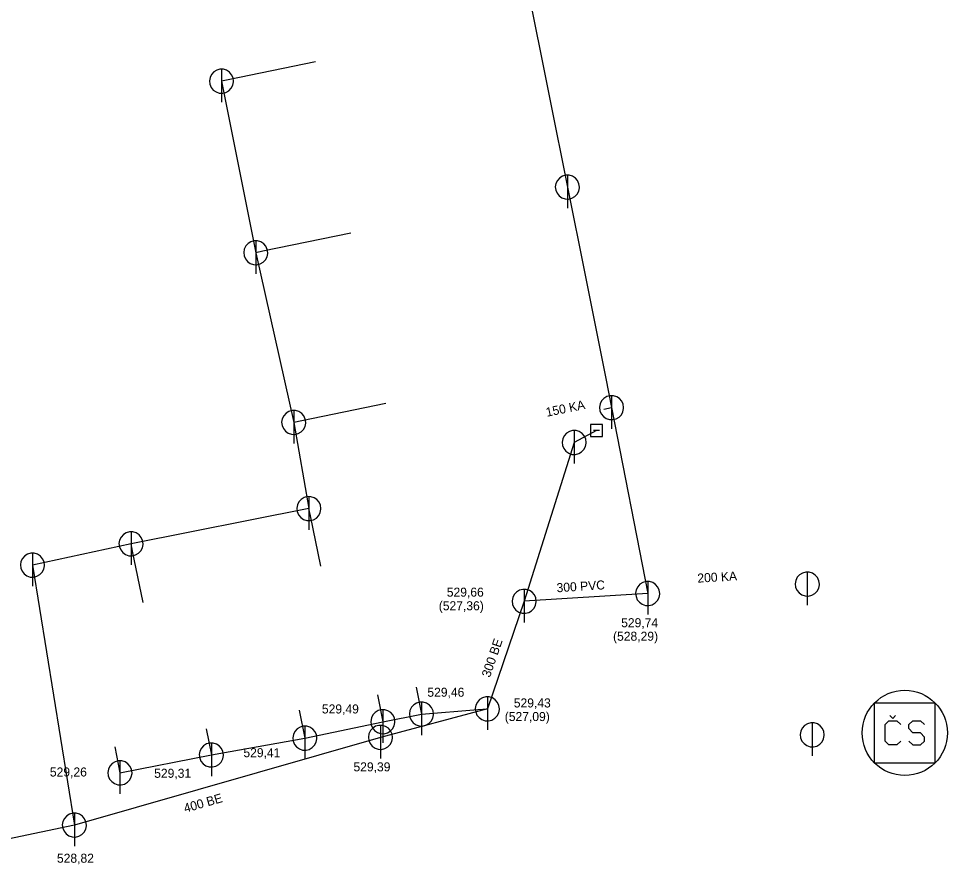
# Model space of a CAD drawing. Extents: x -476058 to -471893, y -1155786 to -1152000.
# Drawn here: x -473406.3 to -473329.3, y -1153901.3 to -1153831.2 of the extents above; entities that cross this region are included whole.
import ezdxf

# ---------------------------------------------------------------- set-up
doc = ezdxf.new("R2010")
doc.units = 0
for name, color, linetype in [('Vrstva 10', 7, 'Continuous'), ('Vrstva 11', 7, 'Continuous'), ('Vrstva 18', 7, 'Continuous'), ('Vrstva 19', 7, 'Continuous'), ('Vrstva 3', 7, 'Continuous'), ('Vrstva 35', 7, 'Continuous'), ('Vrstva 4', 7, 'Continuous'), ('Vrstva 45', 7, 'Continuous'), ('Vrstva 46', 7, 'Continuous'), ('Vrstva 50', 7, 'Continuous')]:
    doc.layers.add(name, color=color, linetype=linetype)

msp = doc.modelspace()

# ---------------------------------------------------------------- linework, layer by layer
at = {"layer": 'Vrstva 10'}
for p, q in [((-473389.52, -1153835.35), (-473389.52, -1153838.098)), ((-473360.833, -1153844.134), (-473360.833, -1153846.882)), ((-473386.68, -1153849.58), (-473386.68, -1153852.328)), ((-473357.167, -1153862.434), (-473357.167, -1153865.182)), ((-473383.53, -1153863.66), (-473383.53, -1153866.408)), ((-473357.925, -1153864.834), (-473358.925, -1153864.834)), ((-473358.925, -1153864.834), (-473358.925, -1153865.834)), ((-473357.925, -1153865.834), (-473357.925, -1153864.834)), ((-473360.268, -1153865.323), (-473360.268, -1153868.071)), ((-473358.925, -1153865.834), (-473357.925, -1153865.834)), ((-473358.175, -1153865.334), (-473358.675, -1153865.334)), ((-473382.27, -1153870.81), (-473382.27, -1153873.558)), ((-473397.02, -1153873.73), (-473397.02, -1153876.478)), ((-473405.2, -1153875.5), (-473405.2, -1153878.248)), ((-473340.934, -1153877.07), (-473340.934, -1153879.818)), ((-473354.173, -1153877.852), (-473354.173, -1153880.6)), ((-473364.413, -1153878.5), (-473364.413, -1153881.248)), ((-473367.47, -1153887.42), (-473367.47, -1153890.168)), ((-473372.936, -1153887.855), (-473372.936, -1153890.603)), ((-473376.138, -1153888.487), (-473376.138, -1153891.235)), ((-473376.337, -1153889.789), (-473376.337, -1153892.537)), ((-473340.524, -1153889.579), (-473340.524, -1153892.327)), ((-473382.608, -1153889.855), (-473382.608, -1153892.603)), ((-473390.36, -1153891.25), (-473390.36, -1153893.998)), ((-473397.94, -1153892.73), (-473397.94, -1153895.478)), ((-473401.72, -1153897.07), (-473401.72, -1153899.818))]:
    msp.add_line(p, q, dxfattribs=at)
for points in [[(-473388.52, -1153836.35), (-473388.559, -1153836.071), (-473388.676, -1153835.814), (-473388.859, -1153835.599), (-473389.095, -1153835.445), (-473389.365, -1153835.362), (-473389.647, -1153835.358), (-473389.919, -1153835.433), (-473390.159, -1153835.581), (-473390.349, -1153835.79), (-473390.472, -1153836.044), (-473390.52, -1153836.322), (-473390.488, -1153836.603), (-473390.379, -1153836.863), (-473390.201, -1153837.082), (-473389.97, -1153837.244), (-473389.702, -1153837.334), (-473389.42, -1153837.346), (-473389.146, -1153837.278), (-473388.902, -1153837.137), (-473388.707, -1153836.933), (-473388.577, -1153836.683), (-473388.521, -1153836.406), (-473388.52, -1153836.35)], [(-473359.833, -1153845.134), (-473359.872, -1153844.855), (-473359.989, -1153844.598), (-473360.172, -1153844.383), (-473360.408, -1153844.229), (-473360.678, -1153844.146), (-473360.96, -1153844.142), (-473361.232, -1153844.217), (-473361.472, -1153844.365), (-473361.662, -1153844.574), (-473361.785, -1153844.828), (-473361.833, -1153845.106), (-473361.801, -1153845.387), (-473361.692, -1153845.647), (-473361.514, -1153845.866), (-473361.283, -1153846.028), (-473361.015, -1153846.118), (-473360.733, -1153846.13), (-473360.459, -1153846.062), (-473360.215, -1153845.921), (-473360.02, -1153845.717), (-473359.89, -1153845.467), (-473359.834, -1153845.19), (-473359.833, -1153845.134)], [(-473385.68, -1153850.58), (-473385.719, -1153850.301), (-473385.836, -1153850.044), (-473386.019, -1153849.829), (-473386.255, -1153849.675), (-473386.525, -1153849.592), (-473386.807, -1153849.588), (-473387.079, -1153849.663), (-473387.319, -1153849.811), (-473387.509, -1153850.02), (-473387.632, -1153850.274), (-473387.68, -1153850.552), (-473387.648, -1153850.833), (-473387.539, -1153851.093), (-473387.361, -1153851.312), (-473387.13, -1153851.474), (-473386.862, -1153851.564), (-473386.58, -1153851.576), (-473386.306, -1153851.508), (-473386.062, -1153851.367), (-473385.867, -1153851.163), (-473385.737, -1153850.913), (-473385.681, -1153850.636), (-473385.68, -1153850.58)], [(-473356.167, -1153863.434), (-473356.206, -1153863.155), (-473356.323, -1153862.898), (-473356.506, -1153862.683), (-473356.742, -1153862.529), (-473357.012, -1153862.446), (-473357.294, -1153862.442), (-473357.566, -1153862.517), (-473357.806, -1153862.665), (-473357.996, -1153862.874), (-473358.119, -1153863.128), (-473358.167, -1153863.406), (-473358.135, -1153863.687), (-473358.026, -1153863.947), (-473357.848, -1153864.166), (-473357.617, -1153864.328), (-473357.349, -1153864.418), (-473357.067, -1153864.43), (-473356.793, -1153864.362), (-473356.549, -1153864.221), (-473356.354, -1153864.017), (-473356.224, -1153863.767), (-473356.168, -1153863.49), (-473356.167, -1153863.434)], [(-473382.53, -1153864.66), (-473382.569, -1153864.381), (-473382.686, -1153864.124), (-473382.869, -1153863.909), (-473383.105, -1153863.755), (-473383.375, -1153863.672), (-473383.657, -1153863.668), (-473383.929, -1153863.743), (-473384.169, -1153863.891), (-473384.359, -1153864.1), (-473384.482, -1153864.354), (-473384.53, -1153864.632), (-473384.498, -1153864.913), (-473384.389, -1153865.173), (-473384.211, -1153865.392), (-473383.98, -1153865.554), (-473383.712, -1153865.644), (-473383.43, -1153865.656), (-473383.156, -1153865.588), (-473382.912, -1153865.447), (-473382.717, -1153865.243), (-473382.587, -1153864.993), (-473382.531, -1153864.716), (-473382.53, -1153864.66)], [(-473359.268, -1153866.323), (-473359.307, -1153866.044), (-473359.424, -1153865.787), (-473359.607, -1153865.572), (-473359.843, -1153865.418), (-473360.113, -1153865.335), (-473360.395, -1153865.331), (-473360.667, -1153865.406), (-473360.907, -1153865.554), (-473361.097, -1153865.763), (-473361.22, -1153866.017), (-473361.268, -1153866.295), (-473361.236, -1153866.576), (-473361.127, -1153866.836), (-473360.949, -1153867.055), (-473360.718, -1153867.217), (-473360.45, -1153867.307), (-473360.168, -1153867.319), (-473359.894, -1153867.251), (-473359.65, -1153867.11), (-473359.455, -1153866.906), (-473359.325, -1153866.656), (-473359.269, -1153866.379), (-473359.268, -1153866.323)], [(-473381.27, -1153871.81), (-473381.309, -1153871.531), (-473381.426, -1153871.274), (-473381.609, -1153871.059), (-473381.845, -1153870.905), (-473382.115, -1153870.822), (-473382.397, -1153870.818), (-473382.669, -1153870.893), (-473382.909, -1153871.041), (-473383.099, -1153871.25), (-473383.222, -1153871.504), (-473383.27, -1153871.782), (-473383.238, -1153872.063), (-473383.129, -1153872.323), (-473382.951, -1153872.542), (-473382.72, -1153872.704), (-473382.452, -1153872.794), (-473382.17, -1153872.806), (-473381.896, -1153872.738), (-473381.652, -1153872.597), (-473381.457, -1153872.393), (-473381.327, -1153872.143), (-473381.271, -1153871.866), (-473381.27, -1153871.81)], [(-473396.02, -1153874.73), (-473396.059, -1153874.451), (-473396.176, -1153874.194), (-473396.359, -1153873.979), (-473396.595, -1153873.825), (-473396.865, -1153873.742), (-473397.147, -1153873.738), (-473397.419, -1153873.813), (-473397.659, -1153873.961), (-473397.849, -1153874.17), (-473397.972, -1153874.424), (-473398.02, -1153874.702), (-473397.988, -1153874.983), (-473397.879, -1153875.243), (-473397.701, -1153875.462), (-473397.47, -1153875.624), (-473397.202, -1153875.714), (-473396.92, -1153875.726), (-473396.646, -1153875.658), (-473396.402, -1153875.517), (-473396.207, -1153875.313), (-473396.077, -1153875.063), (-473396.021, -1153874.786), (-473396.02, -1153874.73)], [(-473404.2, -1153876.5), (-473404.239, -1153876.221), (-473404.356, -1153875.964), (-473404.539, -1153875.749), (-473404.775, -1153875.595), (-473405.045, -1153875.512), (-473405.327, -1153875.508), (-473405.599, -1153875.583), (-473405.839, -1153875.731), (-473406.029, -1153875.94), (-473406.152, -1153876.194), (-473406.2, -1153876.472), (-473406.168, -1153876.753), (-473406.059, -1153877.013), (-473405.881, -1153877.232), (-473405.65, -1153877.394), (-473405.382, -1153877.484), (-473405.1, -1153877.496), (-473404.826, -1153877.428), (-473404.582, -1153877.287), (-473404.387, -1153877.083), (-473404.257, -1153876.833), (-473404.201, -1153876.556), (-473404.2, -1153876.5)], [(-473339.934, -1153878.07), (-473339.973, -1153877.791), (-473340.09, -1153877.534), (-473340.273, -1153877.319), (-473340.509, -1153877.165), (-473340.779, -1153877.082), (-473341.061, -1153877.078), (-473341.333, -1153877.153), (-473341.573, -1153877.301), (-473341.763, -1153877.51), (-473341.886, -1153877.764), (-473341.934, -1153878.042), (-473341.902, -1153878.323), (-473341.793, -1153878.583), (-473341.615, -1153878.802), (-473341.384, -1153878.964), (-473341.116, -1153879.054), (-473340.834, -1153879.066), (-473340.56, -1153878.998), (-473340.316, -1153878.857), (-473340.121, -1153878.653), (-473339.991, -1153878.403), (-473339.935, -1153878.126), (-473339.934, -1153878.07)], [(-473353.173, -1153878.852), (-473353.212, -1153878.573), (-473353.329, -1153878.316), (-473353.512, -1153878.101), (-473353.748, -1153877.947), (-473354.018, -1153877.864), (-473354.3, -1153877.86), (-473354.572, -1153877.935), (-473354.812, -1153878.083), (-473355.002, -1153878.292), (-473355.125, -1153878.546), (-473355.173, -1153878.824), (-473355.141, -1153879.105), (-473355.032, -1153879.365), (-473354.854, -1153879.584), (-473354.623, -1153879.746), (-473354.355, -1153879.836), (-473354.073, -1153879.848), (-473353.799, -1153879.78), (-473353.555, -1153879.639), (-473353.36, -1153879.435), (-473353.23, -1153879.185), (-473353.174, -1153878.908), (-473353.173, -1153878.852)], [(-473363.413, -1153879.5), (-473363.452, -1153879.221), (-473363.569, -1153878.964), (-473363.752, -1153878.749), (-473363.988, -1153878.595), (-473364.258, -1153878.512), (-473364.54, -1153878.508), (-473364.812, -1153878.583), (-473365.052, -1153878.731), (-473365.242, -1153878.94), (-473365.365, -1153879.194), (-473365.413, -1153879.472), (-473365.381, -1153879.753), (-473365.272, -1153880.013), (-473365.094, -1153880.232), (-473364.863, -1153880.394), (-473364.595, -1153880.484), (-473364.313, -1153880.496), (-473364.039, -1153880.428), (-473363.795, -1153880.287), (-473363.6, -1153880.083), (-473363.47, -1153879.833), (-473363.414, -1153879.556), (-473363.413, -1153879.5)], [(-473366.47, -1153888.42), (-473366.509, -1153888.141), (-473366.626, -1153887.884), (-473366.809, -1153887.669), (-473367.045, -1153887.515), (-473367.315, -1153887.432), (-473367.597, -1153887.428), (-473367.869, -1153887.503), (-473368.109, -1153887.651), (-473368.299, -1153887.86), (-473368.422, -1153888.114), (-473368.47, -1153888.392), (-473368.438, -1153888.673), (-473368.329, -1153888.933), (-473368.151, -1153889.152), (-473367.92, -1153889.314), (-473367.652, -1153889.404), (-473367.37, -1153889.416), (-473367.096, -1153889.348), (-473366.852, -1153889.207), (-473366.657, -1153889.003), (-473366.527, -1153888.753), (-473366.471, -1153888.476), (-473366.47, -1153888.42)], [(-473371.936, -1153888.855), (-473371.975, -1153888.576), (-473372.092, -1153888.319), (-473372.275, -1153888.104), (-473372.511, -1153887.95), (-473372.781, -1153887.867), (-473373.063, -1153887.863), (-473373.335, -1153887.938), (-473373.575, -1153888.086), (-473373.765, -1153888.295), (-473373.888, -1153888.549), (-473373.936, -1153888.827), (-473373.904, -1153889.108), (-473373.795, -1153889.368), (-473373.617, -1153889.587), (-473373.386, -1153889.749), (-473373.118, -1153889.839), (-473372.836, -1153889.851), (-473372.562, -1153889.783), (-473372.318, -1153889.642), (-473372.123, -1153889.438), (-473371.993, -1153889.188), (-473371.937, -1153888.911), (-473371.936, -1153888.855)], [(-473375.138, -1153889.487), (-473375.177, -1153889.208), (-473375.294, -1153888.951), (-473375.477, -1153888.736), (-473375.713, -1153888.582), (-473375.983, -1153888.499), (-473376.265, -1153888.495), (-473376.537, -1153888.57), (-473376.777, -1153888.718), (-473376.967, -1153888.927), (-473377.09, -1153889.181), (-473377.138, -1153889.459), (-473377.106, -1153889.74), (-473376.997, -1153890), (-473376.819, -1153890.219), (-473376.588, -1153890.381), (-473376.32, -1153890.471), (-473376.038, -1153890.483), (-473375.764, -1153890.415), (-473375.52, -1153890.274), (-473375.325, -1153890.07), (-473375.195, -1153889.82), (-473375.139, -1153889.543), (-473375.138, -1153889.487)], [(-473375.337, -1153890.789), (-473375.376, -1153890.51), (-473375.493, -1153890.253), (-473375.676, -1153890.038), (-473375.912, -1153889.884), (-473376.182, -1153889.801), (-473376.464, -1153889.797), (-473376.736, -1153889.872), (-473376.976, -1153890.02), (-473377.166, -1153890.229), (-473377.289, -1153890.483), (-473377.337, -1153890.761), (-473377.305, -1153891.042), (-473377.196, -1153891.302), (-473377.018, -1153891.521), (-473376.787, -1153891.683), (-473376.519, -1153891.773), (-473376.237, -1153891.785), (-473375.963, -1153891.717), (-473375.719, -1153891.576), (-473375.524, -1153891.372), (-473375.394, -1153891.122), (-473375.338, -1153890.845), (-473375.337, -1153890.789)], [(-473339.524, -1153890.579), (-473339.563, -1153890.3), (-473339.68, -1153890.043), (-473339.863, -1153889.828), (-473340.099, -1153889.674), (-473340.369, -1153889.591), (-473340.651, -1153889.587), (-473340.923, -1153889.662), (-473341.163, -1153889.81), (-473341.353, -1153890.019), (-473341.476, -1153890.273), (-473341.524, -1153890.551), (-473341.492, -1153890.832), (-473341.383, -1153891.092), (-473341.205, -1153891.311), (-473340.974, -1153891.473), (-473340.706, -1153891.563), (-473340.424, -1153891.575), (-473340.15, -1153891.507), (-473339.906, -1153891.366), (-473339.711, -1153891.162), (-473339.581, -1153890.912), (-473339.525, -1153890.635), (-473339.524, -1153890.579)], [(-473381.608, -1153890.855), (-473381.647, -1153890.576), (-473381.764, -1153890.319), (-473381.947, -1153890.104), (-473382.183, -1153889.95), (-473382.453, -1153889.867), (-473382.735, -1153889.863), (-473383.007, -1153889.938), (-473383.247, -1153890.086), (-473383.437, -1153890.295), (-473383.56, -1153890.549), (-473383.608, -1153890.827), (-473383.576, -1153891.108), (-473383.467, -1153891.368), (-473383.289, -1153891.587), (-473383.058, -1153891.749), (-473382.79, -1153891.839), (-473382.508, -1153891.851), (-473382.234, -1153891.783), (-473381.99, -1153891.642), (-473381.795, -1153891.438), (-473381.665, -1153891.188), (-473381.609, -1153890.911), (-473381.608, -1153890.855)], [(-473389.36, -1153892.25), (-473389.399, -1153891.971), (-473389.516, -1153891.714), (-473389.699, -1153891.499), (-473389.935, -1153891.345), (-473390.205, -1153891.262), (-473390.487, -1153891.258), (-473390.759, -1153891.333), (-473390.999, -1153891.481), (-473391.189, -1153891.69), (-473391.312, -1153891.944), (-473391.36, -1153892.222), (-473391.328, -1153892.503), (-473391.219, -1153892.763), (-473391.041, -1153892.982), (-473390.81, -1153893.144), (-473390.542, -1153893.234), (-473390.26, -1153893.246), (-473389.986, -1153893.178), (-473389.742, -1153893.037), (-473389.547, -1153892.833), (-473389.417, -1153892.583), (-473389.361, -1153892.306), (-473389.36, -1153892.25)], [(-473396.94, -1153893.73), (-473396.979, -1153893.451), (-473397.096, -1153893.194), (-473397.279, -1153892.979), (-473397.515, -1153892.825), (-473397.785, -1153892.742), (-473398.067, -1153892.738), (-473398.339, -1153892.813), (-473398.579, -1153892.961), (-473398.769, -1153893.17), (-473398.892, -1153893.424), (-473398.94, -1153893.702), (-473398.908, -1153893.983), (-473398.799, -1153894.243), (-473398.621, -1153894.462), (-473398.39, -1153894.624), (-473398.122, -1153894.714), (-473397.84, -1153894.726), (-473397.566, -1153894.658), (-473397.322, -1153894.517), (-473397.127, -1153894.313), (-473396.997, -1153894.063), (-473396.941, -1153893.786), (-473396.94, -1153893.73)], [(-473400.72, -1153898.07), (-473400.759, -1153897.791), (-473400.876, -1153897.534), (-473401.059, -1153897.319), (-473401.295, -1153897.165), (-473401.565, -1153897.082), (-473401.847, -1153897.078), (-473402.119, -1153897.153), (-473402.359, -1153897.301), (-473402.549, -1153897.51), (-473402.672, -1153897.764), (-473402.72, -1153898.042), (-473402.688, -1153898.323), (-473402.579, -1153898.583), (-473402.401, -1153898.802), (-473402.17, -1153898.964), (-473401.902, -1153899.054), (-473401.62, -1153899.066), (-473401.346, -1153898.998), (-473401.102, -1153898.857), (-473400.907, -1153898.653), (-473400.777, -1153898.403), (-473400.721, -1153898.126), (-473400.72, -1153898.07)]]:
    msp.add_lwpolyline(points, dxfattribs=at)
at = {"layer": 'Vrstva 11'}
for p, q in [((-473335.348, -1153887.918), (-473330.348, -1153887.918)), ((-473335.348, -1153892.918), (-473335.348, -1153887.918)), ((-473330.348, -1153887.918), (-473330.348, -1153892.918)), ((-473330.348, -1153892.918), (-473335.348, -1153892.918))]:
    msp.add_line(p, q, dxfattribs=at)
for points in [[(-473333.848, -1153889.213), (-473334.084, -1153888.977)], [(-473333.848, -1153889.213), (-473333.612, -1153888.977)], [(-473333.171, -1153891.103), (-473333.502, -1153891.418), (-473334.163, -1153891.418), (-473334.478, -1153891.103), (-473334.478, -1153889.733), (-473334.163, -1153889.418), (-473333.502, -1153889.418), (-473333.171, -1153889.733)], [(-473332.51, -1153891.103), (-473332.195, -1153891.418), (-473331.534, -1153891.418), (-473331.203, -1153891.103), (-473331.203, -1153890.772), (-473331.534, -1153890.41), (-473332.195, -1153890.41), (-473332.51, -1153890.064), (-473332.51, -1153889.733), (-473332.195, -1153889.418), (-473331.534, -1153889.418), (-473331.203, -1153889.733)]]:
    msp.add_lwpolyline(points, dxfattribs=at)
msp.add_circle((-473332.849, -1153890.419), 3.536, dxfattribs=at)
at = {"layer": 'Vrstva 35'}
for points in [[(-473389.52, -1153836.35), (-473386.68, -1153850.58)], [(-473386.68, -1153850.58), (-473383.53, -1153864.66)], [(-473383.53, -1153864.66), (-473382.27, -1153871.81)], [(-473382.27, -1153871.81), (-473397.02, -1153874.73)], [(-473397.02, -1153874.73), (-473405.2, -1153876.5)], [(-473405.2, -1153876.5), (-473401.72, -1153898.07)]]:
    msp.add_lwpolyline(points, dxfattribs=at)
at = {"layer": 'Vrstva 45'}
for points in [[(-473354.173, -1153878.852), (-473364.413, -1153879.5)], [(-473364.413, -1153879.5), (-473367.47, -1153888.42)], [(-473367.47, -1153888.42), (-473376.337, -1153890.789)], [(-473376.337, -1153890.789), (-473401.72, -1153898.07)], [(-473401.72, -1153898.07), (-473410.56, -1153899.92)]]:
    msp.add_lwpolyline(points, dxfattribs=at)
at = {"layer": 'Vrstva 46'}
for points in [[(-473364.287, -1153827.895), (-473362.297, -1153837.829)], [(-473362.297, -1153837.829), (-473360.833, -1153845.134)], [(-473360.833, -1153845.134), (-473359.37, -1153852.439)], [(-473359.37, -1153852.439), (-473357.654, -1153861.004)], [(-473357.654, -1153861.004), (-473357.167, -1153863.434)], [(-473357.799, -1153863.563), (-473357.167, -1153863.434)], [(-473357.167, -1153863.434), (-473354.173, -1153878.852)]]:
    msp.add_lwpolyline(points, dxfattribs=at)
at = {"layer": 'Vrstva 50'}
for p, q in [((-473373.38, -1153886.619), (-473372.936, -1153888.855)), ((-473376.582, -1153887.256), (-473376.138, -1153889.487)), ((-473383.068, -1153888.545), (-473382.608, -1153890.855)), ((-473390.791, -1153890.081), (-473390.36, -1153892.25))]:
    msp.add_line(p, q, dxfattribs=at)
for points in [[(-473381.709, -1153834.749), (-473388.976, -1153836.238), (-473389.52, -1153836.35)], [(-473378.795, -1153848.964), (-473386.09, -1153850.459), (-473386.68, -1153850.58)], [(-473375.898, -1153863.094), (-473382.85, -1153864.521), (-473383.53, -1153864.66)], [(-473358.425, -1153865.334), (-473360.268, -1153866.323), (-473364.244, -1153878.964), (-473364.413, -1153879.5)], [(-473381.288, -1153876.584), (-473382.149, -1153872.396), (-473382.27, -1153871.81)], [(-473396.015, -1153879.612), (-473396.895, -1153875.337), (-473397.02, -1153874.73)], [(-473376.138, -1153889.487), (-473372.936, -1153888.855)], [(-473372.936, -1153888.855), (-473368.265, -1153888.483), (-473367.47, -1153888.42)], [(-473382.608, -1153890.855), (-473376.138, -1153889.487)], [(-473390.36, -1153892.25), (-473382.608, -1153890.855)], [(-473398.366, -1153891.587), (-473397.94, -1153893.73), (-473390.36, -1153892.25)]]:
    msp.add_lwpolyline(points, dxfattribs=at)

# ---------------------------------------------------------------- texts
at = {"layer": 'Vrstva 18'}
for s, rotation, p in [('300 PVC', 3.62092, (-473361.705, -1153878.755)), ('300 BE', 71.08274, (-473367.258, -1153885.868)), ('400 BE', 16.0053, (-473392.527, -1153897.049))]:
    msp.add_text(s, height=0.75, rotation=rotation, dxfattribs=at).set_placement(p)
at = {"layer": 'Vrstva 19'}
for s, rotation, p in [('150 KA', 11.59286, (-473362.537, -1153864.194)), ('200 KA', 3.38193, (-473350.029, -1153877.956))]:
    msp.add_text(s, height=0.75, rotation=rotation, dxfattribs=at).set_placement(p)
at = {"layer": 'Vrstva 3'}
for s, p in [('529,66', (-473370.834, -1153879.116)), ('529,74', (-473356.374, -1153881.652)), ('529,46', (-473372.444, -1153887.418)), ('529,49', (-473381.192, -1153888.806)), ('529,43', (-473365.278, -1153888.307)), ('529,41', (-473387.702, -1153892.436)), ('529,39', (-473378.574, -1153893.61)), ('529,26', (-473403.752, -1153894.037)), ('529,31', (-473395.103, -1153894.144)), ('528,82', (-473403.166, -1153901.191))]:
    msp.add_text(s, height=0.75, dxfattribs=at).set_placement(p)
at = {"layer": 'Vrstva 4'}
for s, p in [('(527,36)', (-473371.5, -1153880.245)), ('(528,29)', (-473357.046, -1153882.772)), ('(527,09)', (-473366.026, -1153889.435))]:
    msp.add_text(s, height=0.75, dxfattribs=at).set_placement(p)

doc.saveas('drawing.dxf')
